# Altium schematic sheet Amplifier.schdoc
size A4; Organization: Altium Limited; Address1: L3, 12a Rodborough Rd; Address2: Frenchs Forest; Address3: NSW; Address4: Australia 2086
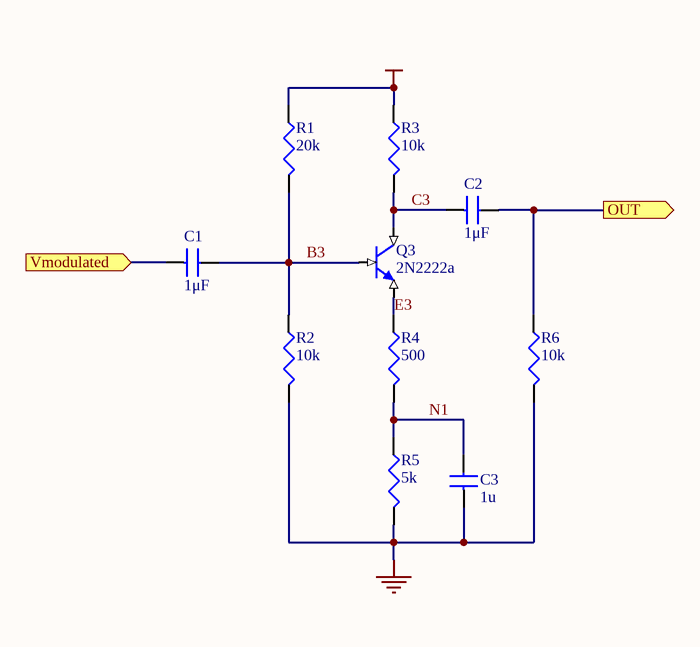
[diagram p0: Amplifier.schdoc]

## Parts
C1  1μF
C2  1μF
C3  1u
Q3  2N2222a
R1  20k
R2  10k
R3  10k
R4  500
R5  5k
R6  10k

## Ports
OUT (out), Vmodulated (in)

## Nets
GND: C3.1 R2.1(TOP) R5.1(TOP) R6.1(TOP)
VCC: R1.2(BOT) R3.2(BOT)
B3: C1.2 Q3.2(B) R1.1(TOP) R2.2(BOT)
C3: C2.1 Q3.1(C) R3.1(TOP)
E3: Q3.3(E) R4.2(BOT)
N1: C3.2 R4.1(TOP) R5.2(BOT)
OUT: C2.2 R6.2(BOT) ; port OUT
Vmodulated: C1.1 ; port Vmodulated

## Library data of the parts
C1-C3 = CAP: Capacitor
Q3 = 2N2222a: NPN BJT
R1-R6 = RES: Resistor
